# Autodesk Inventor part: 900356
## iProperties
Created: 2007-12
Part Number: 900356
Document SubType Name: Modeling
Designer: SW
Density: 1.06 g/cm^3
Categories: <MemberInstance><Categories><Category DisplayName="" Mnemonic="CABLEANDHARNESS" InternalName="e4a7e005-5e42-4d16-b293-125e7f0d0512"><Category DisplayName="" Mne
Mass: 6.1454 g
Surface Area: 63.7869 cm^2
Volume: 5.79754 cm^3
Material: ABS Plastic
Description: M60 POWER WIRE CONNECTOR
GlobalPropertyList: <PropertyList/>
Component Category: Electrical
Author: SW
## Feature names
1. Base1
